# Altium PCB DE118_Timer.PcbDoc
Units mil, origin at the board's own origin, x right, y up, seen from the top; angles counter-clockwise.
Board outline 3937.01 x 3149.61 mil, 2 copper layers (Component Side, Bottom Layer), stack 4.3 mil thick; 32 components, 48 nets, 197 pads, 12 vias.
Unrouted connection lines stored in the file: 1.
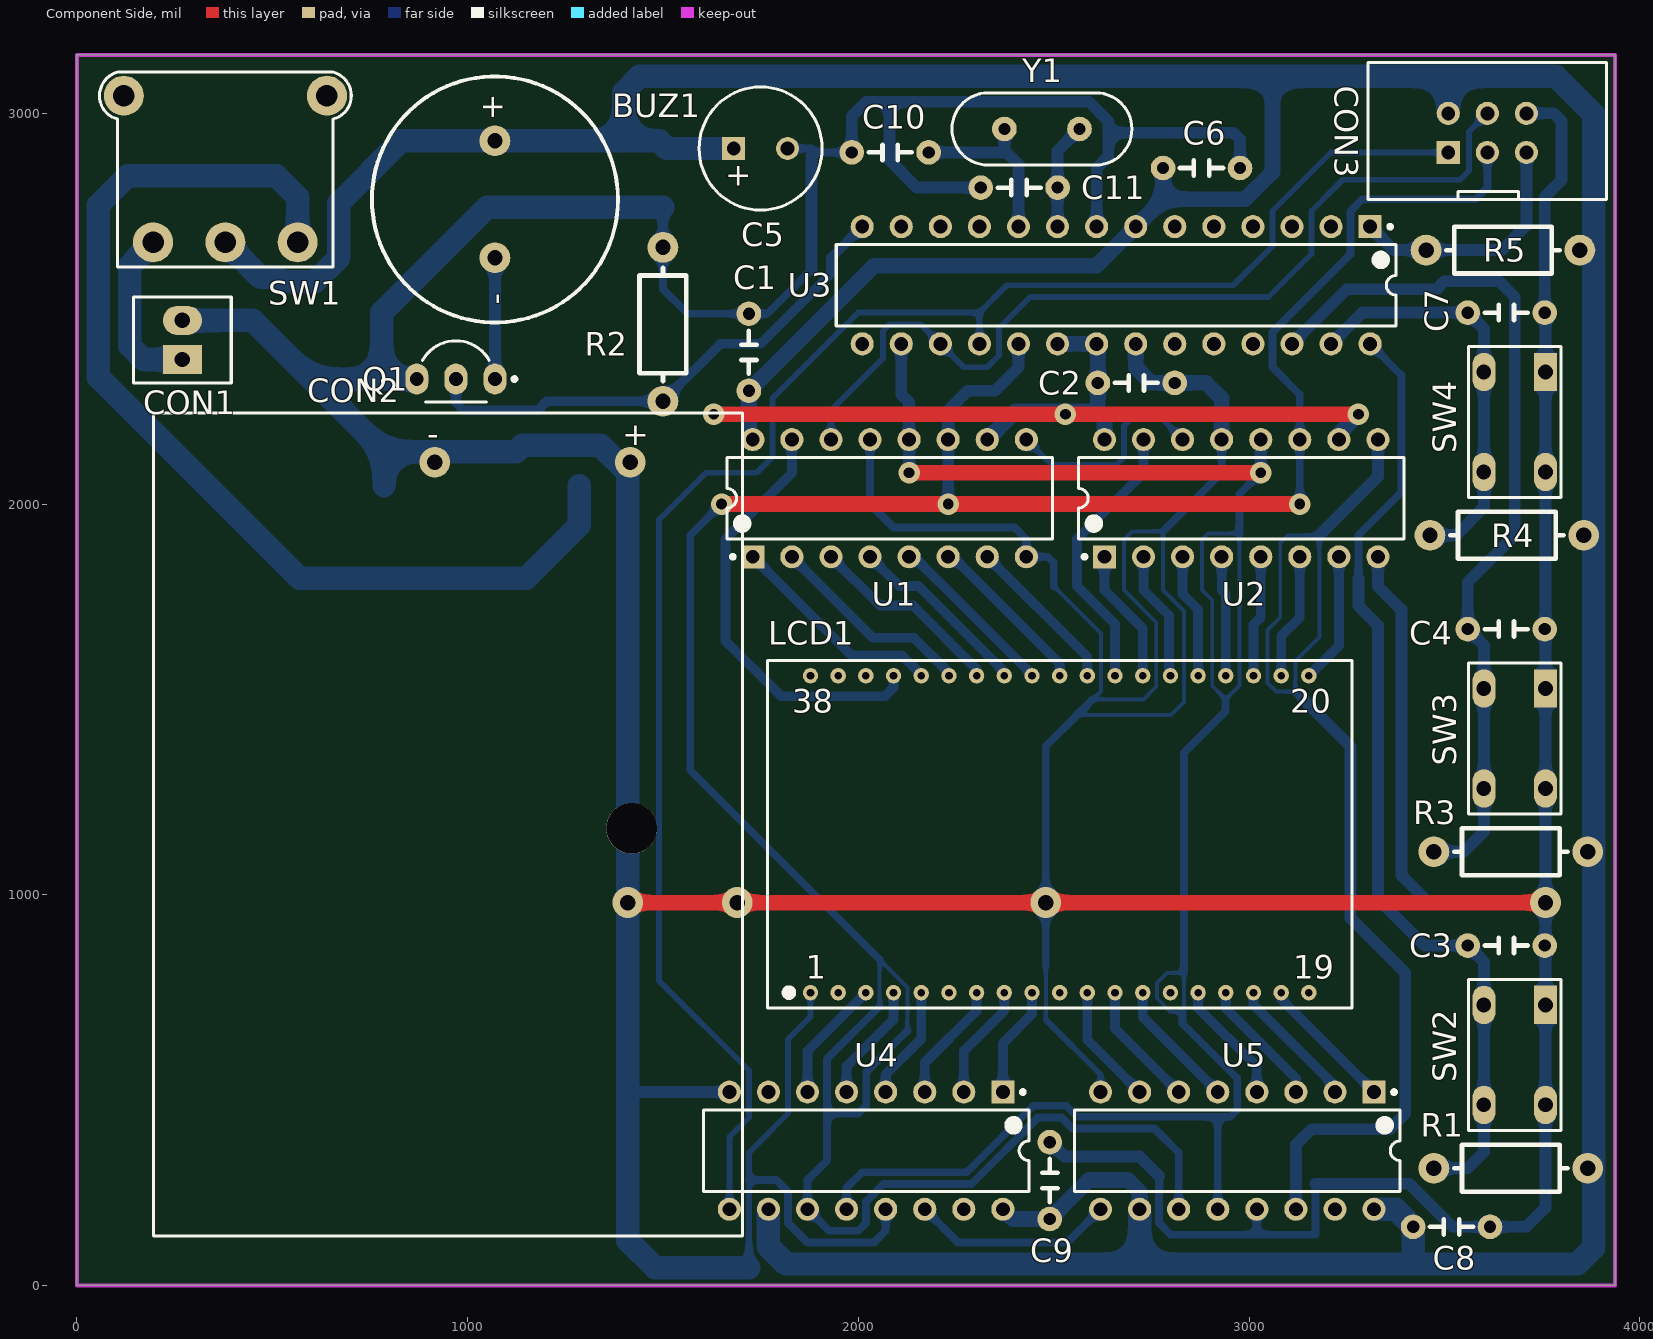
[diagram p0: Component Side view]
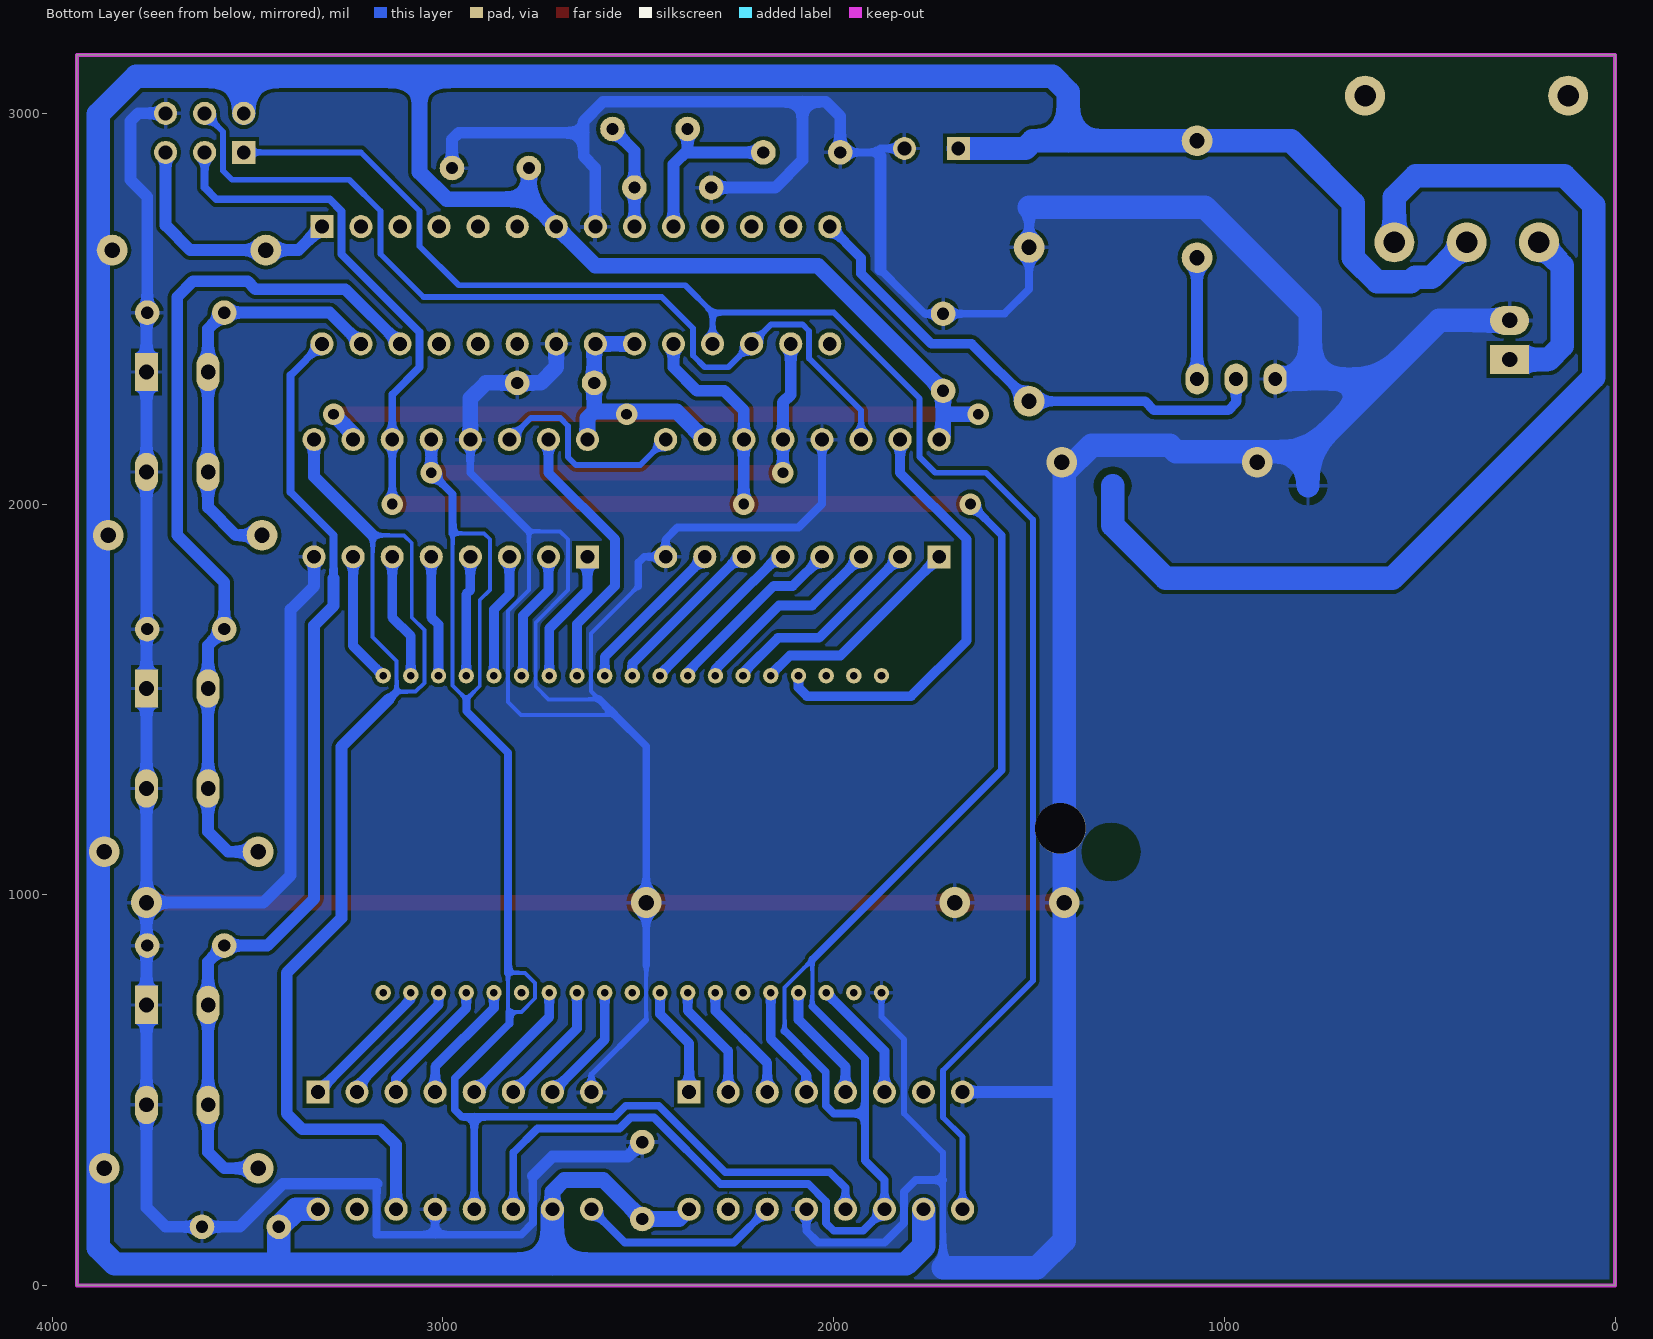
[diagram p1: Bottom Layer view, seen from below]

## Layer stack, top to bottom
Top Solder: solder mask 0.4, Solder Resist, Dk 3.5
Component Side: signal copper 1.4
Dielectric 1: core 1.5, FR-4, Dk 4.2
Bottom Layer: signal copper 1.4
Solder Side: solder mask 0.4, Solder Resist, Dk 3.5

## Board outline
0,0 3937.01,0 3937.01,3149.61 0,3149.61

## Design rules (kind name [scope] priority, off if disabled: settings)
Clearance ShieldClearance_BOT [InNamedPolygon('GND_BOT') vs InNet('SHIELD')] p1: gap=30 ignorepadtopadclearanceinfootprint=FALSE
Clearance ShieldClearance_TOP [InNamedPolygon('GND_TOP') vs InNet('SHIELD')] p2: gap=30 ignorepadtopadclearanceinfootprint=FALSE
Clearance [All] p3: gap=10 ignorepadtopadclearanceinfootprint=FALSE
DiffPairsRouting DiffPair_100_2DiffPairsRouting [InDifferentialPairClass('DIFF100_2')] p1: maxlimit=10 minlimit=10 mostfreqgap=10 toplayer_minwidth=8 toplayer_maxwidth=15 toplayer_prefwidth=15 bottomlayer_minwidth=8 bottomlayer_maxwidth=15 bottomlayer_prefwidth=15 maxuncoupledlength=500
DiffPairsRouting DiffPair_100DiffPairsRouting [InDifferentialPairClass('DIFF100')] p2: maxlimit=10 minlimit=10 mostfreqgap=10 toplayer_minwidth=8 toplayer_maxwidth=15 toplayer_prefwidth=15 bottomlayer_minwidth=8 bottomlayer_maxwidth=15 bottomlayer_prefwidth=15 maxuncoupledlength=500
DiffPairsRouting [All] p3: maxlimit=10 minlimit=8 mostfreqgap=8 toplayer_minwidth=8 toplayer_maxwidth=30 toplayer_prefwidth=8 bottomlayer_minwidth=8 bottomlayer_maxwidth=30 bottomlayer_prefwidth=8 maxuncoupledlength=500
Height [All] p1: minheight=0 maxheight=1200 prefheight=500
HoleSize [All] p1: absolutevalues=TRUE maxlimit=200 minlimit=1 maxpercent=80.000 minpercent=20.000
MatchedLengths DiffPair_100_2MatchedLengths [InNetClass('DIFF100_A')] p1: tolerance=1000 checknetsindiffpair=TRUE checkdiffpairvsdiffpair=FALSE checkxsignals=FALSE checkothers=FALSE
MatchedLengths DiffPair_100MatchedLengths [InNetClass('DIFF100_B')] p2: tolerance=5 checknetsindiffpair=TRUE checkdiffpairvsdiffpair=FALSE checkxsignals=FALSE checkothers=FALSE
MinimumSolderMaskSliver [All] p1: minsoldermaskwidth=1
PasteMaskExpansion [InNet('230V_N')] p1: expansion=20
PlaneClearance [All] p1: clearance=10
PlaneConnect MotConnect [InNetClass('MOT[6..1]')] p1: planeconnectstyle=Direct reliefexpansion=20 reliefentries=4 reliefconductorwidth=10 reliefairgap=10
PlaneConnect ComConnect [InNetClass('COM[6..1]')] p2: planeconnectstyle=Direct reliefexpansion=20 reliefentries=4 reliefconductorwidth=10 reliefairgap=10
PlaneConnect ShieldConnect [InNet('SHIELD')] p3: planeconnectstyle=Relief reliefexpansion=20 reliefentries=4 reliefconductorwidth=10 reliefairgap=40
PlaneConnect [All] p4: planeconnectstyle=Relief reliefexpansion=8 reliefentries=4 reliefconductorwidth=8 reliefairgap=5
PolygonConnect [All] p1: connectstyle=Relief reliefconductorwidth=10 reliefentries=4 polygonreliefangle="90 Angle" airgapwidth=10
RoutingVias [All] p1: holewidth=5.91 width=11.81 viastyle="Through Hole" minholewidth=5.91 minwidth=11.81 maxholewidth=500 maxwidth=1000
SilkToSilkClearance [All] p1: silktosilkclearance=5
SilkToSolderMaskClearance SilkscreenOverComponentPads [IsPad] p1: minsilkscreentomaskgap=1 clearancetoexposedcopper=TRUE
SolderMaskExpansion [InNet('230V_N')] p1: expansion=5 istentingtop=FALSE
Width GND [InNet('GND')] p1: maxlimit=100 minlimit=8 preferedwidth=50
Width 3V3 [InNet('3V3')] p2: maxlimit=40 minlimit=8 preferedwidth=30
Width 5V [InNet('5V')] p3: maxlimit=90 minlimit=10 preferedwidth=60
Width 24V [InNet('24V')] p4: maxlimit=80 minlimit=10 preferedwidth=60
Width [All] p5: maxlimit=100 minlimit=6 preferedwidth=8
21 further rules are at their usual default settings.

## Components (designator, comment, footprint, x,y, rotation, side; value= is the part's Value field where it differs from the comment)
BUZ1 "BUZZER" BUZZER-14mm 1070,2780 r270 top
C1 "100nF" CAP-5x2.5 1720,2486.85 r270 top
C2 "100nF" CAP-5x2.5 2810,2310 r180 top
C3 "100nF" CAP-5x2.5 3756.85,870 r180 top
C4 "100nF" CAP-5x2.5 3756.85,1680 r180 top
C5 "1uF" CAPPR3.5-8x12 1750,2910 r0 top
C6 "100nF" CAP-5x2.5 2976.85,2860 r180 top
C7 "100nF" CAP-5x2.5 3756.85,2490 r180 top
C8 "100nF" CAP-5x2.5 3616.85,150 r180 top
C9 "100nF" CAP-5x2.5 2490,366.85 r270 top
C10 "15pF" CAP-5x2.5 1983.15,2900 r0 top
C11 "15pF" CAP-5x2.5 2313.15,2810 r0 top
CON1 "MX-02227-2021" MX-02227-2021 270,2420 r90 top
CON2 "KEYS2460" BAT_HOLDER_2479RB 1416.06,2107.01 r0 top
CON3 "Header 3X2" HDR2X3_IDC 3510,2900 r0 top
LCD1 "DE118-RS-20/6.35" DE118 2515.39,1155 r0 top locked
Q1 "2N7000" TO92_WIDE 920,2320 r0 top
R1 "10k" RES_AXIAL_0W25 3670,300 r0 top
R2 "10k" RES_AXIAL_0W25 1500,2460 r270 top
R3 "10k" RES_AXIAL_0W25 3670,1110 r0 top
R4 "10k" RES_AXIAL_0W25 3660,1920 r0 top
R5 "10k" RES_AXIAL_0W25 3650,2650 r0 top
SW1 "5MS1S12AM6QE" 5MS1S12AM6QE 380,2670 r180 top
SW2 "DTSHW66NB" FSM2J 3680,590 r270 top
SW3 "DTSHW66NB" FSM2J 3680,1400 r270 top
SW4 "DTSHW66NB" FSM2J 3680,2210 r270 top
U1 "74HC595" DIP16 2080,2015 r90 top
U2 "74HC595" DIP16 2980,2015 r90 top
U3 "ATmega88PA-PU" DIP28 2660,2560 r270 top
U4 "74HC595" DIP16 2020,345 r270 top
U5 "74HC595" DIP16 2970,345 r270 top
Y1 "32k" HC-49U 2470,2960 r180 top

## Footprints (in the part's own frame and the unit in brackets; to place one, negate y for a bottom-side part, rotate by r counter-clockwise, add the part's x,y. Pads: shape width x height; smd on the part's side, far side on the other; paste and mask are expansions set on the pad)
5MS1S12AM6QE [mm] "spdt switch"
  round 2.6 hole 1.4: 1(4.7,0) 2(0,0) 3(-4.7,0) ""(-6.605,-9.53) ""(6.605,-9.53)
  silkscreen extent -8.19,-11.06 8.19,1.6, body extent -6.71,-15.64 6.71,0.6, height 6.7
BAT_HOLDER_2479RB [mm] "Holds Three (3) “AAA” Cells in Series"
  round 2 hole 1: 1(0,0) 2(-12.7,0)
  round 3.3 hole 3.3: ""(0.1,-23.8)
  silkscreen extent -31,-50.3 7.3,3.2, body extent -83.76,-50.08 7.05,2.9, height 13.78
BUZZER-14mm [mm]
  round 2 hole 1: 1(-3.8,0) 2(3.8,0)
  silkscreen extent -7.99,-8 8.01,8, body extent -6.98,-7 7,7, height 7.35
CAP-5x2.5 [mm]
  round 1.6 hole 0.8: 1(0,0) 2(5,0)
  silkscreen extent 1.1,-0.5 3.9,0.5, body extent -0.39,-1.59 5.39,1.59, height 5
CAPPR3.5-8x12 [mm] "Capacitor, Electrolytic, Radial; Body 8 x 12 mm (Dia.xH typ); Pin Spacing 3.5 mm (typ)"
  rect 1.5x1.5 hole 0.9: 1(-1.75,0)
  round 1.5 hole 0.9: 2(1.75,0)
  silkscreen extent -4,-4 4,4, body extent -4,-4 3.98,4, height 12.01
DE118 [mm] "DISPLAY ELEKTRONIK DE 118-RS-20/6,35/M"
  round 1 hole 0.5: 1(-16.2,-10.3) 2(-14.4,-10.3) 3(-12.6,-10.3) 4(-10.8,-10.3) 5(-9,-10.3) 6(-7.2,-10.3) 7(-5.4,-10.3) 8(-3.6,-10.3) 9(-1.8,-10.3) 10(0,-10.3) 11(1.8,-10.3) 12(3.6,-10.3) 13(5.4,-10.3) 14(7.2,-10.3) 15(9,-10.3) 16(10.8,-10.3) 17(12.6,-10.3) 18(14.4,-10.3) 19(16.2,-10.3) 20(16.2,10.3) 21(14.4,10.3) 22(12.6,10.3) 23(10.8,10.3) 24(9,10.3) 25(7.2,10.3) 26(5.4,10.3) 27(3.6,10.3) 28(1.8,10.3) 29(0,10.3) 30(-1.8,10.3) 31(-3.6,10.3) 32(-5.4,10.3) 33(-7.2,10.3) 34(-9,10.3) 35(-10.8,10.3) 36(-12.6,10.3) 37(-14.4,10.3) 38(-16.2,10.3)
  silkscreen extent -19,-11.3 19,11.3
DIP16 [mm]
  rect 1.5x1.5 hole 0.9: 1(-3.81,8.89)
  round 1.5 hole 0.9: 2(-3.81,6.35) 3(-3.81,3.81) 4(-3.81,1.27) 5(-3.81,-1.27) 6(-3.81,-3.81) 7(-3.81,-6.35) 8(-3.81,-8.89) 9(3.81,-8.89) 10(3.81,-6.35) 11(3.81,-3.81) 12(3.81,-1.27) 13(3.81,1.27) 14(3.81,3.81) 15(3.81,6.35) 16(3.81,8.89)
  silkscreen extent -3.93,-10.58 2.65,10.58, body extent -5.08,-10.16 5.08,10.16, height 9.1
DIP28 [mm] "28-Pin Plastic Dual In-Line Package (PDIP)"
  rect 1.5x1.5 hole 0.9: 1(-3.81,16.51)
  round 1.5 hole 0.9: 2(-3.81,13.97) 3(-3.81,11.43) 4(-3.81,8.89) 5(-3.81,6.35) 6(-3.81,3.81) 7(-3.81,1.27) 8(-3.81,-1.27) 9(-3.81,-3.81) 10(-3.81,-6.35) 11(-3.81,-8.89) 12(-3.81,-11.43) 13(-3.81,-13.97) 14(-3.81,-16.51) 15(3.81,-16.51) 16(3.81,-13.97) 17(3.81,-11.43) 18(3.81,-8.89) 19(3.81,-6.35) 20(3.81,-3.81) 21(3.81,-1.27) 22(3.81,1.27) 23(3.81,3.81) 24(3.81,6.35) 25(3.81,8.89) 26(3.81,11.43) 27(3.81,13.97) 28(3.81,16.51)
  silkscreen extent -3.93,-18.2 2.65,18.2, body extent -5.08,-18 5.08,18, height 9.08
FSM2J [mm]
  rect 2.5x1.5 hole 0.95: 1(-3.25,2)
  oval 2.5x1.5 hole 0.95: 1(3.25,2) 2(-3.25,-2) 2(3.25,-2)
  silkscreen extent -4.9,-3 4.9,3, body extent -4.13,-3.3 4.13,3.2, height 7
HC-49U [mm] "Quartz Crystal, Thru-Hole; 2 Leads; Body 11.35 x 4.65 x 13.46 mm (LxWxH max)"
  round 1.6 hole 0.8: 1(-2.44,0) 2(2.44,0)
  silkscreen extent -5.85,-2.35 5.85,2.35, body extent -5.67,-2.3 5.68,2.35, height 3.6
HDR2X3_IDC [mm] "Connector; Header; 3x2 Position"
  rect 1.5x1.5 hole 0.9: 1(0,0)
  round 1.5 hole 0.9: 2(0,2.54) 3(2.54,0) 4(2.54,2.54) 5(5.08,0) 6(5.08,2.54)
  silkscreen extent -5.21,-3.05 10.29,5.84, body extent -5.07,-3.01 10.15,5.84, height 8.93
MX-02227-2021 [mm]
  rect 1.905x2.54 hole 1: 1(-1.27,0)
  oval 1.905x2.54 hole 1: 2(1.27,0)
  silkscreen extent -2.79,-3.18 2.79,3.17, body extent -2.54,-2.92 2.54,2.88, height 11.7
RES_AXIAL_0W25 [mm]
  round 2 hole 1: 1(-4.999,0) 2(4.999,0)
  silkscreen extent -3.68,-1.52 3.68,1.52, body extent -5.38,-1.2 5.38,1.2, height 2.2
TO92_WIDE [mm]
  oval 1.5x2 hole 0.9: 1(3.81,0) 2(1.27,0) 3(-1.27,0)
  silkscreen extent -0.9,-1.5 5.21,2.48, body extent -1.5,-1.55 4.04,2.55, height 6.7

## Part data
C1 C2 C3 C4 C6 C7 C8 C9 C10 C11: library part Cap, "Capacitor"
C5: library part "Capacitor Tantalum", "Capacitor Tantalum"
CON1: "Pith 2.54mm, 2-pin"
CON2: "Holds Three (3) “AAA” Cells in Series"
CON3: "Header, 3-Pin, Dual row"
LCD1: "Wyœwietlacz: LCD; cyfrowy; STN Positive; Il.cyfr:4; Znak:8mm"
R1 R2 R3 R4 R5: library part Resistor, "Resistor"
SW2 SW3 SW4: "SWITCH, SPNO TACT"
U1 U2 U4 U5: "8-bit serial-in, serial or parallel-out shift register with output latches; 3-state"
U3: "8-bit AVR Microcontroller, 8KB Flash, 512 Bytes EEPROM, 1KB SRAM, 28-pin PDIP, Industrial Grade (-40°C to 85°C)"
Y1: library part XTAL, "Crystal Oscillator"

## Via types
v1: diameter 55.12, hole 27.56, Component Side to Bottom Layer, tented both sides, 8 vias
v2: diameter 78.74, hole 39.37, Component Side to Bottom Layer, tented both sides, 4 vias

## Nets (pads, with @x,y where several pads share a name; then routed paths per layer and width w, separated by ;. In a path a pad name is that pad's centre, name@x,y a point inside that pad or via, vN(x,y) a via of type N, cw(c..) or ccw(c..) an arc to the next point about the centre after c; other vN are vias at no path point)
#CS: U1.12 U2.12 U3.16 U4.12 U5.12 | length 5227.9
  Component Side w40: v1(2130,2080) v1(3030,2080)
  Bottom Layer w10: 2764.17,735.12 2799.29,700 2830,700 2833.54,703.54 2833.54,800 2790,800 2764.17,774.17 2764.17,735.12 ; 2880,1780 2880,1910 2894.72,1924.72 2975.28,1924.72 2975.28,1535.28 2940,1500 2905.91,1534.09 2905.91,1754.09 2880,1780
  Bottom Layer w20: U4.12 1970,250 2010,290 2277.57,290 2447.57,460 2532.43,460 2560.58,431.85 2920,431.85 ; 2830,700 2830,670 2970,530 2970,450 2951.85,431.85 2920,431.85 ; 2833.54,800 2833.54,1363.54 2940,1470 2940,1500 ; U5.12 2920,431.85 ; 2975.28,1924.72 2975.28,2025.28 v1(3030,2080)
  Bottom Layer w30: U3.16 2110,2280 2130,2260 U1.12 v1(2130,2080) ; v1(3030,2080) U2.12
#RST: CON3.5 R5.1 U3.1 | length 637.9
  Bottom Layer w30: U3.1 3370,2650 R5.1 3646.85,2650 3710,2713.15 CON3.5
BTN1: C3.2 R1.1 SW2.2 U3.28 | length 2490.1
  Bottom Layer w20: 3280,1810 3280,1920 3390,2030 3390,2330 U3.28
  Bottom Layer w30: 3280,1810 3280,1740 3330,1690 3330,990 3450,870 C3.2 3601.26,828.74 3601.26,717.95 3601.26,462.05 3601.26,341.26 3560,300 R1.1
BTN2: C4.2 R3.1 SW3.2 U3.26 | length 2237.7
  Bottom Layer w30: U3.26 3250,2550 3480,2550 3500,2570 3640,2570 3680,2530 3680,1920 3560,1800 C4.2 3601.26,1638.74 3601.26,1527.95 3601.26,1272.05 3601.26,1161.26 3550,1110 R3.1
BTN3: C7.2 R4.1 SW4.2 U3.27 | length 1066.6
  Bottom Layer w30: U3.27 3290,2490 C7.2 3601.26,2448.74 3601.26,2337.95 3601.26,2082.05 3601.26,1991.26 3530,1920 R4.1
BUZZ: Q1.2 R2.2 U3.14 | length 1326.4
  Bottom Layer w25: Q1.2 970,2260 990,2240 1180,2240 1203.19,2263.19 R2.2 1646.81,2410 1750,2410 1930,2590 1930,2630 U3.14
GND: C1.1 C2.1 C3.1 C4.1 C5.2 C6.1 C7.1 C8.1 C9.1 C10.1 C11.1 CON1.2 CON2.2 CON3.6 LCD1.1 Q1.3 R2.1 SW2.1 SW3.1 SW4.1 U1.8 U1.13 U2.8 U2.13 U3.8 U3.22 U4.8 U4.13 U5.8 U5.13 | length 22161.6
  Component Side w40: v2(1410,980) v2(2480,980) v2(3758.74,980)
  Bottom Layer w10: 2479.96,680.04 2479.96,820 ; 2500,1790 2620.94,1669.05 2620.94,1520.94 2600,1500 2730,1500 2762.68,1532.68 2762.68,1697.32 2680,1780 2680,1910 2700,1930 2780,1930 2780,1780 2833.54,1726.46 2833.54,1493.54 2800,1460 2560,1460
  Bottom Layer w15: 1410,490 1415,495 ; 1720,45 1720,270 1720,340 1820,440 1820,630 1877.6,687.6 LCD1.1 ; 2479.96,680.04 2620,540 U5.8
  Bottom Layer w20: 1500,2760 R2.1 1500,2550 1563.15,2486.85 C1.1 1766.85,2486.85 1880,2600 ; 1720,270 1790,270 1820,240 1820,160 1870,110 2040,110 2070,140 U4.13 ; C5.2 1880,2910 1890,2900 C10.1 ; U1.13 2030,2000 2090,1940 2400,1940 2430,1910 U1.8 2485,1865 2500,1850 2500,1790 ; 2479.96,820 2479.96,1379.96 2560,1460 2600,1500 ; 2770,280 2770,160 2800,130 3020,130 ; 2780,1930 2930,2080 U2.13 ; U5.13 3020,130 ; 3170,260 3170,130 3020,130
  Bottom Layer w30: 1415,495 U4.8 ; 1880,2600 1880,2890 1890,2900 ; C10.1 1983.15,2992.76 2020,3029.61 2080,3029.61 ; C11.1 2150,2810 2080,2880 2080,3029.61 ; C9.1 2526.85,330 2720,330 2770,280 ; U3.8 2610,2860 2640,2890 2640,2950 ; C6.1 2976.85,2933.15 2960,2950 2640,2950 ; 3170,260 3410,260 3520,150 C8.1 3710,150 3758.74,198.74 3758.74,462.05 3758.74,717.95 v2(3758.74,980) ; U2.8 3330,1790 3390,1730 3390,1050 3460,980 v2(3758.74,980) ; CON3.6 3780,3000 3800,2980 3800,2830 3756.85,2786.85 C7.1 ; C7.1@3746.85,2490 3758.74,2478.11 3758.74,2337.95 3758.74,2082.05 3758.74,1527.95 3758.74,1272.05 v2(3758.74,980) ; 2080,3029.61 2590.5,3029.61 2640,2980.1 2640,2950
  Bottom Layer w40: U3.22 2710,2350 2750,2310 C2.1 2890,2310 2930,2270 U2.13
  Bottom Layer w60: CON1.2 450,2470 600,2320 ; 786.06,2046.61 786.06,2133.94 ; Q1.3 780,2320 ; 1500,2760 1050,2760 780,2490 780,2320 ; 1720,45 1480,45 1410,115 1410,490 1410,2080 1340,2150 1140,2150 1123.94,2133.94 786.06,2133.94 ; 600,2320 780,2320 ; 600,2320 786.06,2133.94
  other v2: 1690,980
MISO: CON3.1 U3.18 U4.9 | length 4510.9
  Bottom Layer w15: U4.9 1670,380 1720,430 1720,550 1490,780 1490,1960 1610,2080 1740,2080 1780,2120 1780,2270 2000,2490 2310,2490 ; U3.18 2310,2490 ; CON3.1 3210,2900 3060,2750 3060,2660 2960,2560 2380,2560 2310,2490
MOSI: CON3.4 U1.14 U3.17 | length 2366
  Bottom Layer w15: U1.14 1930,2240 2062.97,2372.97 2062.97,2442.97 2080,2460 2160,2460 U3.17 2270,2350 2330,2350 2360,2380 2360,2450 2440,2530 3050,2530 3160,2640 3160,2750 3240,2830 3540,2830 3562.97,2852.97 3562.97,2952.97 CON3.4
NetBUZ1_2: BUZ1.2 Q1.1 | length 310.4
  Bottom Layer w30: Q1.1 BUZ1.2
NetC10_2: C10.2 U3.10 Y1.2 | length 458.9
  Bottom Layer w30: C10.2 2373.94,2900 ; Y1.2 2373.94,2906.06 2410,2870 U3.10
NetC11_2: C11.2 U3.9 Y1.1 | length 273.2
  Bottom Layer w30: U3.9 C11.2 2510,2903.94 Y1.1
NetCON1_1: CON1.1 SW1.1 | length 439.3
  Bottom Layer w60: SW1.1 135,2610.04 135,2405 170,2370 CON1.1
NetCON2_1: CON2.1 SW1.3 | length 2720.2
  Bottom Layer w60: SW1.3 565.04,2784.96 510,2840 130,2840 55,2765 55,2325 570,1810 1150,1810 1286.06,1946.06 1286.06,2046.61
NetLCD1_3: LCD1.3 U4.6 | length 316.3
  Bottom Layer w25: U4.6 1870,600.16 LCD1.3
NetLCD1_4: LCD1.4 U4.5 | length 304.3
  Bottom Layer w25: U4.5 1970,560 2090.2,680.2 LCD1.4
NetLCD1_5: LCD1.5 U4.4 | length 296.5
  Bottom Layer w25: U4.4 2070,540 2161.06,631.06 LCD1.5 LCD1.5@2156.77,749.49
NetLCD1_7: LCD1.7 U4.3 | length 309.5
  Bottom Layer w25: U4.3 2170,570 2302.8,702.8 LCD1.7
NetLCD1_8: LCD1.8 U4.2 | length 297.4
  Bottom Layer w25: U4.2 2270,600 2373.66,703.66 LCD1.8
NetLCD1_9: LCD1.9 U4.1 | length 285.4
  Bottom Layer w25: U4.1 2370,620 2444.53,694.53 LCD1.9
NetLCD1_11: LCD1.11 U5.7 | length 309.9
  Bottom Layer w25: LCD1.11 2586.26,628.74 U5.7
NetLCD1_12: LCD1.12 U5.6 | length 322
  Bottom Layer w25: LCD1.12 2657.13,657.87 U5.6
NetLCD1_13: LCD1.13 U5.5 | length 334
  Bottom Layer w25: LCD1.13 2727.99,687.01 U5.5
NetLCD1_15: LCD1.15 U5.4 | length 322.9
  Bottom Layer w25: LCD1.15 2869.72,710.28 3020,560 3020,510 U5.4@3005,495
NetLCD1_16: LCD1.16 U5.3 | length 328.8
  Bottom Layer w25: LCD1.16 2940.59,709.41 3120,530 U5.3
NetLCD1_17: LCD1.17 U5.2 | length 340.9
  Bottom Layer w25: LCD1.17 3011.46,718.54 3220,510 U5.2
NetLCD1_18: LCD1.18 U5.1 | length 352.9
  Bottom Layer w25: LCD1.18 3082.32,732.68 U5.1
NetLCD1_20: LCD1.20 U2.7 | length 336.3
  Bottom Layer w25: LCD1.20 3230,1637.32 U2.7
NetLCD1_21: LCD1.21 U2.6 | length 324.2
  Bottom Layer w25: LCD1.21 3082.32,1662.32 3130,1710 U2.6
NetLCD1_22: LCD1.22 U2.5 | length 312.2
  Bottom Layer w25: LCD1.22 3011.46,1691.46 3030,1710 U2.5
NetLCD1_23: LCD1.23 U2.4 | length 308.9
  Bottom Layer w25: U2.4 2930,1780 2940.59,1769.41 LCD1.23
NetLCD1_24: LCD1.24 U2.3 | length 320.9
  Bottom Layer w25: U2.3 2830,1770 2869.72,1730.28 LCD1.24
NetLCD1_25: LCD1.25 U2.2 | length 333
  Bottom Layer w25: U2.2 2730,1780 2795,1715 2795,1564.37 LCD1.25
NetLCD1_26: LCD1.26 U2.1 | length 345.1
  Bottom Layer w25: U2.1 2630,1780 2727.99,1682.01 LCD1.26
NetLCD1_27: LCD1.27 U2.15 | length 715.1
  Bottom Layer w25: LCD1.27 2657.13,1692.87 2560,1790 2560,1910 2730,2080 U2.15
NetLCD1_28: LCD1.28 U1.7 | length 410.6
  Bottom Layer w25: U1.7 2586.26,1608.74 LCD1.28
NetLCD1_29: LCD1.29 U1.6 | length 429.9
  Bottom Layer w25: U1.6 2242.28,1865 2515.39,1591.89 LCD1.29
NetLCD1_30: LCD1.30 U1.5 | length 446.9
  Bottom Layer w25: U1.5 2142.97,1865 2167.97,1840 2167.97,1839.31 2204.31,1802.97 2205,1802.97 LCD1.30@2445.99,1561.98 ; LCD1.30 LCD1.30@2444.53,1565.47
NetLCD1_31: LCD1.31 U1.4 | length 475.3
  Bottom Layer w25: U1.4 2105,1790 2153.64,1790 2373.66,1569.98 LCD1.31
NetLCD1_32: LCD1.32 U1.3 | length 508.7
  Bottom Layer w25: U1.3 2055,1740 2140,1740 2302.8,1577.2 LCD1.32
NetLCD1_33: LCD1.33 U1.2 | length 535
  Bottom Layer w25: U1.2 2037.3,1657.7 2142.3,1657.7 2227.64,1572.36 2227.64,1560.51 LCD1.33
NetLCD1_34: LCD1.34 U1.1 | length 558.9
  Bottom Layer w25: U1.1 1982.3,1612.7 2111.81,1612.7 2161.06,1563.45 LCD1.34
NetLCD1_35: LCD1.35 U1.15 | length 1113.7
  Bottom Layer w25: U1.15 1830,2080 1660,1910 1660,1650 1801.67,1508.33 2068.33,1508.33 2090.2,1530.2 LCD1.35
QDS1: U1.9 U2.14 | length 546.3
  Bottom Layer w15: U1.9 2495,2100 2660,2100 2680,2120 2680,2200 2700,2220 2775,2220 U2.14
QDS2: U2.9 U5.14 | length 2966.8
  Bottom Layer w10: 3047.64,1542.36 3070,1520 3118.5,1520 3118.5,1598.5 3180,1660 3180,1920 3100,1920 3080,1900 3080,1710 3047.64,1677.64 3047.64,1542.36
  Bottom Layer w20: 3118.5,1520 3138.5,1500
  Bottom Layer w30: U5.14 3120,360 3160,400 3360,400 3400,440 3400,800 3260,940 3260,1378.5 3138.5,1500 ; 3180,1920 3330,2070 U2.9
QDS3: U4.14 U5.9 | length 525.4
  Bottom Layer w20: U4.14@2170,200 U4.14 2255,110 2535,110 U5.9
SCK: CON3.3 U1.11 U2.11 U3.19 U4.11 U5.11 | length 7320.5
  Component Side w40: v1(1650,2000) v1(2230,2000) v1(3130,2000)
  Bottom Layer w10: 2054.76,714.76 2054.76,833.97 2125.63,763.11 2125.63,651.59
  Bottom Layer w20: v1(1650,2000) 1570,1920 1570,1318.74 2054.76,833.97 ; 2054.76,714.76 1920,580 1920,440 ; 2125.63,651.59 2020.47,546.43 2020.47,460.47 2000,440 1920,440 ; U5.11 2820,340 2758.15,401.85 2548.15,401.85 2520,430 2460,430 2290,260 2064.96,260 2020,215.04 2020,160 2000,140 1925,140 U4.11 1870,270 1920,320 1920,440 ; v1@3130,1990 v1(3130,2000) U2.11 3130,2280 3060,2350 3060,2440 3259.53,2639.53 3259.53,2749.53 3290,2780 3580,2780 3610,2810 CON3.3
  Bottom Layer w30: v1(2230,2000) U1.11 2230,2240 2280,2290 2350,2290 2410,2350 U3.19
VIN: BUZ1.1 C1.2 C2.2 C5.1 C6.2 C8.2 C9.2 CON3.2 R1.2 R3.2 R4.2 R5.2 SW1.2 U1.10 U1.16 U2.10 U2.16 U3.7 U3.20 U3.21 U4.10 U4.16 U5.10 U5.16 | length 14820.6
  Component Side w40: v1(1630,2230) v1(2530,2230) 3230,2230 v1(3280,2230)
  Bottom Layer w40: v1(1630,2230) 1717.5,2230 1720,2232.5 ; U1.16 1720,2175 1720,2232.5 ; U1.10 2401.85,2236.85 2613.15,2236.85 ; U4.16 2395,170 C9.2 2590,270 2690,270 2720,240 U5.10 ; U3.20 U3.21 2613.15,2406.85 C2.2 2613.15,2236.85 ; U2.16 2630,2220 2613.15,2236.85 ; C6.2 2780,2780 ; 3060,3094.61 3060,2850 2990,2780 2780,2780 ; U2.10 3230,2180 v1(3280,2230) ; 1720,2232.5 C1.2 2040,2610 2610,2610 U3.7 2780,2780
  Bottom Layer w60: SW1.2 470,2580 511.95,2580 523.13,2568.82 608.82,2568.82 670,2630 670,2770 829.61,2929.61 BUZ1.1 1399.61,2929.61 ; C5.1 1510,2910 1490.39,2929.61 1399.61,2929.61 ; U4.10 1770,100 1815,55 2720,55 ; U5.10 2720,55 ; U5.16 3375,195 C8.2 3420,65 3410,55 ; CON3.2 3510,3094.61 ; 1399.61,2929.61 1399.61,3054.21 1440,3094.61 3060,3094.61 3510,3094.61 ; 2720,55 3410,55 ; 3410,55 3840,55 3882.01,97.01 3882.01,2997.99 3785.39,3094.61 3510,3094.61
pads on no net: CON2. LCD1.2 LCD1.6 LCD1.10 LCD1.14 LCD1.19 LCD1.36 LCD1.37 LCD1.38 SW1. U3.2 U3.3 U3.4 U3.5 U3.6 U3.11 U3.12 U3.13 U3.15 U3.23 U3.24 U3.25 U4.7 U4.15 U5.15

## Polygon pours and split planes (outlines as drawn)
GND on Bottom Layer "GND" (solid, remove dead copper, pour order 0): 0,3149.61 3937.01,3149.61 3937.01,0 0,0

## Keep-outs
Keep-Out Layer:
  the board outline again, w10

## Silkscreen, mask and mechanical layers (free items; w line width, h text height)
Mechanical 1:
  lines w11.81: 3758.74,980 3758.74,980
